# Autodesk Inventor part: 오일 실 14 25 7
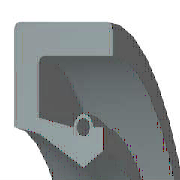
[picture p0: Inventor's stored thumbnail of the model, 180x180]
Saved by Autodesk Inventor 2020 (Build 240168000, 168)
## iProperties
Created: 2012-02
Part Number: 오일 실 14 25 7
Material: 고무
Description: 오일 실 - 스프링 장착, 금속 케이스 SM
Document SubType Name: Modeling
Standard: JIS B 2402
Designer: mdu-01
Standards Organization: JIS
Language: ko-KR
Size Designation: 14 25 7 A
Categories: <MemberInstance><Categories><Category DisplayName="샤프트 부품" InternalName="7f7aeb1f-a693-4053-b835-cee3144e0d98" Mnemonic="SHFT"><Category DisplayName="실링" Intern
Density: 0.93 g/cm^3
Appearance: Rubber-Black
IsCustomPart: 1
Author: mdu-01
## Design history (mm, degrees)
body "Solid1"
revolve "회전1" stored, may be unused: angle "d33" = 360 deg
fillet "모깎기1" dims "d34" = 0.35 (= 0.05 x b)
chamfer "모따기1" distance "d35" = 0.7 (= 0.1 x b); stored, may be unused: second distance "d36" = 0.35 (= 0.05 x b), angle "d41" = 45 deg
sketch "스케치2"
  geometry: L1 (8.336, -5.158)-(8.853, -7); L2 (7.786, -4.55)-(8.336, -5.158); L3 (7, -1.75)-(7.786, -4.55); L4 (7.733, -0.875)-(7, -1.75); L5 (8.963, -0.875)-(7.733, -0.875); L6 (8.963, -1.575)-(8.963, -0.875); L7 (8.963, -5.25)-(8.963, -2.975); L8 (10.3, -5.25)-(8.963, -5.25); L9 (11.4, -1.75)-(10.3, -5.25); L10 (11.4, 0)-(11.4, -1.75); L11 (12.5, 0)-(11.4, 0); L12 (12.5, -7)-(12.5, 0); L13 (8.853, -7)-(12.5, -7); L14 (0, -9.6)-(0, 1.6) reference; L15 (28, 0)-(14, 0) reference; A1 r 0.7 centre (8.963, -2.275) between (8.963, -2.975) and (8.963, -1.575)
  constraints: 26 end point, 4 horizontal, 4 vertical, 2 point on circle, 1 centre point, 1 collinear, 1 parallel
  dimensions: "d2" = 7 distance of L12.start L11.start (= b); "d4" = 0.875 vertical distance of L10.start L5.start (= 0.125 x b); "d6" = 1.1 distance of L11.start L10.start (= 0.1 x dd - 0.1 x Diam); "d8" = 1.75 distance of L10.start L9.start (= 0.25 x b); "d10" = 1.75 vertical distance of L8.start L1.end (= 0.25 x b); "d12" = 1.1 horizontal distance of L9.start L8.start (= 0.1 x dd - 0.1 x Diam); "d14" = 0.7 radius of A1 (= 0.1 x b); "d16" = 0 horizontal distance of A1.centre L7.end; "d18" = 0.7 distance of L6.start L5.start (= 0.1 x b); "d20" = 0.73333 horizontal distance of L4.start L3.start (= 0.0666667 x dd - 0.0666667 x Diam); "d22" = 0.11 horizontal distance of L7.start L1.end (= 0.01 x dd - 0.01 x Diam); "d24" = 0.875 vertical distance of L4.start L3.start (= 0.125 x b); "d26" = 2.8 vertical distance of L3.start L2.start (= 0.4 x b); "d28" = 0.78571 horizontal distance of L3.start L2.start (= 0.0714286 x dd - 0.0714286 x Diam); "d30" = 1.84211 vertical distance of L1.start L1.end (= 0.263158 x b); "d32" = 0.55 horizontal distance of L2.start L1.start (= 0.05 x dd - 0.05 x Diam); "d37" = 0 distance between parallel lines of L15 L11; "d38" = 12.5 distance between parallel lines of L14 L12 (= 0.5 x dd); "d39" = 7 distance from line of L14 L3.start (= 0.5 x Diam)
other parameters: "dd" = 25 [user parameter; used in 7 equation terms], "Diam" = 14 [user parameter; used in 7 equation terms], "b" = 7 [user parameter; used in 12 equation terms], "d1" = 8 (derived), "d3" = 1 (derived), "d5" = 2 (derived), "d7" = 2 (derived), "d9" = 2 (derived), "d11" = 2 (derived), "d13" = 0.8 (derived), "d15" = 0 (derived), "d17" = 0.8 (derived), "d19" = 1.33333 (derived), "d21" = 0.2 (derived), "d23" = 1 (derived), "d25" = 3.2 (derived), "d27" = 1.42857 (derived), "d29" = 2.10526 (derived), "d31" = 1 (derived), "d40" = 0
